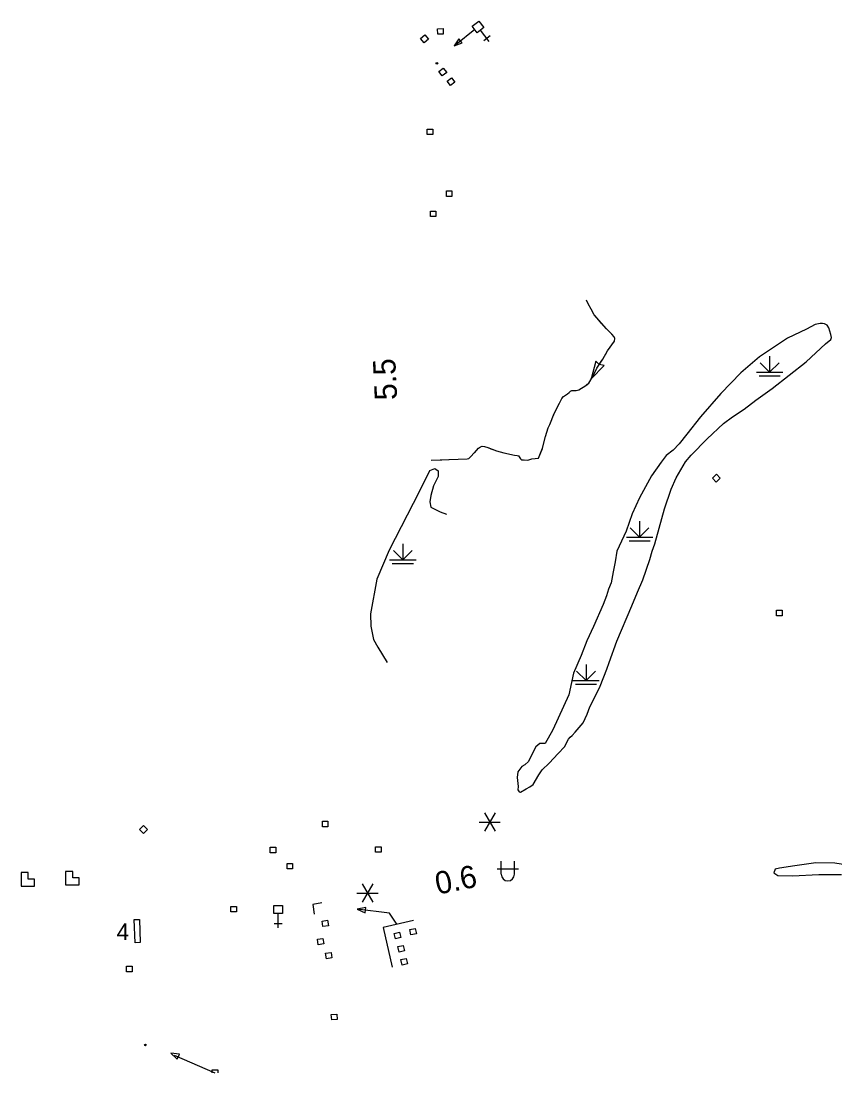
# Model space of a CAD drawing. Extents: x -160 to 6143532, y -375 to 762199.
# Drawn here: x -104.53 to -72.79, y -313.76 to -272.74 of the extents above; entities that cross this region are included whole.
import ezdxf

# ---------------------------------------------------------------- set-up
doc = ezdxf.new("R2010")
doc.units = 0
for name, color, linetype in [('Level 43', 7, 'Continuous'), ('Level 44', 7, 'Continuous'), ('Level 47', 7, 'Continuous'), ('Level 48', 7, 'Continuous'), ('Level 56', 7, 'Continuous'), ('Level 57', 7, 'Continuous'), ('Level 58', 7, 'Continuous')]:
    doc.layers.add(name, color=color, linetype=linetype)

msp = doc.modelspace()

# ---------------------------------------------------------------- linework, layer by layer
at = {"layer": 'Level 43'}
for p, q in [((-82.115, -285.996), (-82.289, -286.685)), ((-82.289, -286.685), (-81.794, -286.175)), ((-81.98, -286.128), (-82.115, -285.996)), ((-81.794, -286.175), (-81.978, -286.129))]:
    msp.add_line(p, q, dxfattribs=at)
for points in [[(-84.352, -289.786), (-84.19, -289.392), (-84.077, -288.931), (-83.976, -288.598), (-83.911, -288.463), (-83.735, -288.046), (-83.529, -287.635), (-83.443, -287.452), (-83.376, -287.38), (-83.214, -287.279), (-83.151, -287.216), (-83.099, -287.173), (-83.052, -287.146), (-82.975, -287.139), (-82.878, -287.142), (-82.779, -287.121), (-82.507, -286.953), (-82.392, -286.858), (-82.221, -286.571), (-82.075, -286.267), (-81.844, -285.923), (-81.652, -285.594), (-81.391, -285.221), (-81.367, -285.111), (-81.398, -285.052), (-81.493, -284.948), (-81.702, -284.744), (-82.176, -284.194), (-82.3, -283.972), (-82.415, -283.758), (-82.471, -283.617)], [(-82.282, -284.004), (-82.3, -283.972), (-82.415, -283.758), (-82.471, -283.617)], [(-81.873, -284.546), (-82.141, -284.236)], [(-81.596, -284.847), (-81.702, -284.744), (-81.873, -284.546)], [(-81.739, -285.743), (-81.652, -285.594), (-81.391, -285.221), (-81.367, -285.111), (-81.398, -285.052), (-81.406, -285.043)], [(-82.289, -286.685), (-82.221, -286.571), (-82.075, -286.267), (-81.88, -285.977)], [(-83.168, -287.234), (-83.151, -287.216), (-83.099, -287.173), (-83.052, -287.146), (-82.975, -287.139), (-82.878, -287.142), (-82.779, -287.121), (-82.507, -286.953), (-82.447, -286.903)], [(-83.765, -288.117), (-83.735, -288.046), (-83.529, -287.635), (-83.443, -287.452), (-83.388, -287.393)], [(-84.129, -289.143), (-84.077, -288.931), (-83.976, -288.598), (-83.911, -288.463), (-83.871, -288.368)], [(-88.529, -289.864), (-87.125, -289.805), (-87.067, -289.792), (-86.999, -289.729), (-86.684, -289.396), (-86.608, -289.342), (-86.54, -289.319), (-86.455, -289.324), (-86.329, -289.369), (-85.991, -289.499), (-85.699, -289.576), (-85.285, -289.67), (-85.179, -289.675), (-85.125, -289.693), (-85.102, -289.724), (-85.052, -289.809), (-85.007, -289.843), (-84.93, -289.847), (-84.782, -289.854), (-84.728, -289.852), (-84.608, -289.802), (-84.352, -289.786)], [(-86.85, -289.571), (-86.684, -289.396), (-86.608, -289.342), (-86.54, -289.319), (-86.455, -289.324), (-86.329, -289.369), (-86.148, -289.439)], [(-85.889, -289.526), (-85.699, -289.576), (-85.285, -289.67), (-85.179, -289.675), (-85.125, -289.693), (-85.105, -289.721)], [(-84.352, -289.786), (-84.196, -289.408)], [(-88.529, -289.864), (-88.12, -289.847)], [(-87.847, -289.836), (-87.125, -289.805), (-87.067, -289.792), (-87.04, -289.767)], [(-84.893, -289.849), (-84.782, -289.854), (-84.728, -289.852), (-84.608, -289.802), (-84.352, -289.786)]]:
    msp.add_lwpolyline(points, dxfattribs=at)
at = {"layer": 'Level 44'}
for p, q in [((-75.335, -285.805), (-75.335, -286.425)), ((-75.335, -286.425), (-75.701, -286.06)), ((-75.335, -286.425), (-74.969, -286.06)), ((-75.852, -286.425), (-74.818, -286.425)), ((-75.749, -286.566), (-74.921, -286.566)), ((-80.405, -292.242), (-80.405, -292.862)), ((-80.922, -292.862), (-79.888, -292.862)), ((-80.405, -292.862), (-80.771, -292.497)), ((-80.405, -292.862), (-80.04, -292.497)), ((-89.635, -293.128), (-89.635, -293.748)), ((-80.819, -293.003), (-79.992, -293.003)), ((-89.635, -293.748), (-90.001, -293.382)), ((-89.635, -293.748), (-89.269, -293.382)), ((-90.152, -293.748), (-89.118, -293.748)), ((-90.049, -293.889), (-89.221, -293.889)), ((-82.496, -298.452), (-82.862, -298.086)), ((-82.496, -297.831), (-82.496, -298.452)), ((-82.496, -298.452), (-82.13, -298.086)), ((-83.013, -298.452), (-81.979, -298.452)), ((-82.91, -298.593), (-82.082, -298.593))]:
    msp.add_line(p, q, dxfattribs=at)
at = {"layer": 'Level 47'}
for points in [[(-73.027, -284.698), (-73.098, -284.597), (-73.202, -284.544), (-73.275, -284.536), (-73.362, -284.536), (-73.554, -284.572), (-73.892, -284.752), (-74.638, -285.102), (-75.735, -285.827), (-76.46, -286.449), (-77.236, -287.263), (-78.037, -288.176), (-78.57, -288.841), (-78.864, -289.221), (-79.092, -289.47), (-79.376, -289.683), (-79.559, -289.937), (-79.945, -290.465), (-80.411, -291.328), (-80.7, -291.952), (-80.929, -292.627), (-81.289, -293.408), (-81.36, -293.825), (-81.441, -294.211), (-81.511, -294.65), (-81.615, -294.893), (-81.702, -295.152), (-81.827, -295.494), (-82.203, -296.349), (-82.46, -296.9), (-82.688, -297.48), (-82.987, -298.166), (-83.163, -299.009), (-83.795, -300.38), (-84.094, -300.904), (-84.292, -300.909), (-84.454, -301.041), (-84.535, -301.178), (-84.733, -301.605), (-84.88, -301.742), (-84.992, -301.802), (-85.154, -302.011), (-85.174, -302.234), (-85.139, -302.589), (-85.154, -302.711), (-85.103, -302.792), (-85.053, -302.802), (-84.824, -302.68), (-84.692, -302.604), (-84.555, -302.508), (-84.337, -302.132), (-84.21, -301.94), (-83.926, -301.671), (-83.587, -301.3), (-83.333, -301.036), (-83.181, -300.742), (-83.115, -300.661), (-83.034, -300.595), (-82.917, -300.468), (-82.612, -300.109), (-82.445, -299.765), (-82.341, -299.476), (-82.161, -299.132), (-81.95, -298.675), (-81.684, -298.009), (-81.593, -297.75), (-81.3, -296.918), (-80.703, -295.536), (-80.485, -295.003), (-80.277, -294.526), (-80.013, -293.738), (-79.912, -293.403), (-79.815, -293.119), (-79.638, -292.51), (-79.44, -291.764), (-79.181, -290.993), (-78.978, -290.551), (-78.618, -289.927), (-78.4, -289.663), (-77.774, -289.024), (-77.135, -288.425), (-76.789, -288.166), (-76.328, -287.867), (-75.876, -287.517), (-75.238, -287.068), (-73.914, -286.023), (-73.156, -285.322), (-72.943, -285.155), (-72.917, -285.074), (-72.948, -284.963), (-73.027, -284.698)], [(-88.582, -290.262), (-89.233, -291.545), (-90.171, -293.365), (-90.65, -294.495), (-90.899, -295.855), (-90.88, -296.334), (-90.784, -296.852), (-90.612, -297.158), (-90.255, -297.75)], [(-88.582, -290.262), (-88.39, -290.185), (-88.256, -290.281), (-88.256, -290.491), (-88.448, -290.855), (-88.544, -291.239), (-88.582, -291.488), (-88.544, -291.698), (-88.18, -291.871), (-87.933, -291.964)], [(-71.641, -305.759), (-72.796, -305.578), (-73.537, -305.561), (-74.347, -305.682), (-74.95, -305.768), (-74.95, -305.768), (-75.122, -305.811), (-75.166, -305.958), (-75.01, -306.052), (-74.45, -306.07), (-73.416, -306.018), (-72.537, -306.018)]]:
    msp.add_lwpolyline(points, dxfattribs=at)
at = {"layer": 'Level 48'}
for p, q in [((-86.044, -303.617), (-86.458, -304.334)), ((-86.458, -303.617), (-86.044, -304.334)), ((-86.665, -303.976), (-85.838, -303.976)), ((-90.811, -306.383), (-91.224, -307.099)), ((-91.224, -306.383), (-90.811, -307.099)), ((-91.431, -306.741), (-90.604, -306.741))]:
    msp.add_line(p, q, dxfattribs=at)
at = {"layer": 'Level 56'}
for points in [[(-88.07, -273.027), (-88.061, -273.242), (-88.276, -273.251), (-88.285, -273.036)], [(-88.642, -273.445), (-88.807, -273.584), (-88.946, -273.419), (-88.781, -273.28)], [(-87.929, -274.745), (-88.101, -274.875), (-88.231, -274.703), (-88.06, -274.573)], [(-87.609, -275.124), (-87.781, -275.254), (-87.911, -275.082), (-87.74, -274.952)], [(-88.691, -277.167), (-88.691, -276.952), (-88.475, -276.952), (-88.475, -277.167)], [(-87.942, -279.577), (-87.942, -279.361), (-87.726, -279.361), (-87.726, -279.577)], [(-88.562, -280.361), (-88.562, -280.145), (-88.346, -280.145), (-88.346, -280.361)], [(-77.262, -290.564), (-77.417, -290.713), (-77.567, -290.558), (-77.412, -290.408)], [(-75.066, -295.928), (-75.066, -295.713), (-74.85, -295.713), (-74.85, -295.928)], [(-92.775, -304.159), (-92.775, -303.944), (-92.559, -303.944), (-92.559, -304.159)], [(-99.754, -304.109), (-99.598, -304.258), (-99.748, -304.414), (-99.903, -304.265)], [(-94.807, -305.169), (-94.807, -304.954), (-94.591, -304.954), (-94.591, -305.169)], [(-90.699, -305.152), (-90.699, -304.937), (-90.483, -304.937), (-90.483, -305.152)], [(-94.153, -305.799), (-94.153, -305.584), (-93.937, -305.584), (-93.937, -305.799)], [(-96.344, -307.476), (-96.344, -307.26), (-96.128, -307.26), (-96.128, -307.476)], [(-91.112, -307.508), (-91.086, -307.299), (-91.413, -307.364)], [(-99.875, -308.67), (-100.082, -308.678), (-100.116, -307.774), (-99.91, -307.766)], [(-92.789, -307.837), (-92.576, -307.802), (-92.542, -308.015), (-92.754, -308.05)], [(-89.93, -308.522), (-89.977, -308.312), (-89.767, -308.265), (-89.719, -308.475)], [(-89.322, -308.376), (-89.369, -308.166), (-89.158, -308.118), (-89.111, -308.328)], [(-92.972, -308.543), (-92.76, -308.508), (-92.725, -308.722), (-92.938, -308.756)], [(-89.783, -309.041), (-89.831, -308.831), (-89.62, -308.783), (-89.573, -308.993)], [(-92.649, -309.09), (-92.437, -309.056), (-92.402, -309.269), (-92.615, -309.303)], [(-89.671, -309.548), (-89.718, -309.338), (-89.507, -309.29), (-89.46, -309.5)], [(-100.409, -309.813), (-100.409, -309.598), (-100.193, -309.598), (-100.193, -309.813)], [(-92.214, -311.461), (-92.198, -311.676), (-92.413, -311.691), (-92.429, -311.477)], [(-98.435, -313.213), (-98.351, -313.02), (-98.683, -312.991)]]:
    msp.add_lwpolyline(points, close=True, dxfattribs=at)
for points in [[(-92.799, -307.127), (-93.148, -307.184), (-93.092, -307.567)], [(-89.869, -307.95), (-90.162, -307.522), (-91.413, -307.364)], [(-89.218, -307.817), (-90.41, -308.085), (-90.055, -309.626)], [(-98.549, -313.067), (-96.963, -313.755)], [(-97.068, -313.757), (-97.068, -313.639), (-96.852, -313.639), (-96.852, -313.757)]]:
    msp.add_lwpolyline(points, dxfattribs=at)
msp.add_circle((-99.677, -312.666), 0.031, dxfattribs=at)
at = {"layer": 'Level 57'}
for p, q in [((-86.267, -273.536), (-86.607, -273.094)), ((-86.239, -273.318), (-86.485, -273.507)), ((-85.803, -306.009), (-85.803, -305.492)), ((-85.286, -306.009), (-85.286, -305.492)), ((-85.958, -305.802), (-85.131, -305.802)), ((-94.505, -308.1), (-94.505, -307.543)), ((-94.35, -307.944), (-94.661, -307.944))]:
    msp.add_line(p, q, dxfattribs=at)
for points in [[(-86.67, -272.736), (-86.474, -272.992), (-86.739, -273.196), (-86.936, -272.94)], [(-87.325, -273.589), (-87.459, -273.426), (-87.637, -273.709)], [(-94.337, -307.22), (-94.337, -307.543), (-94.672, -307.543), (-94.672, -307.22)]]:
    msp.add_lwpolyline(points, close=True, dxfattribs=at)
msp.add_lwpolyline([(-87.568, -273.657), (-86.835, -273.053)], dxfattribs=at)
msp.add_circle((-88.311, -274.383), 0.031, dxfattribs=at)
msp.add_arc((-85.545, -306.009), 0.259, 180, 0, dxfattribs=at)
at = {"layer": 'Level 58'}
for points in [[(-104.526, -306.472), (-104.001, -306.472), (-104.001, -306.195), (-104.249, -306.195), (-104.249, -305.946), (-104.526, -305.946)], [(-102.789, -306.422), (-102.264, -306.422), (-102.264, -306.145), (-102.512, -306.145), (-102.512, -305.897), (-102.789, -305.897)]]:
    msp.add_lwpolyline(points, close=True, dxfattribs=at)

# ---------------------------------------------------------------- texts
at = {"layer": 'Level 48'}
for s, rotation, p in [('5.5', 92.8335, (-89.857, -287.498)), ('0.6', 11.3121, (-88.284, -306.806))]:
    msp.add_text(s, height=0.8737, rotation=rotation, dxfattribs=at).set_placement(p)
at = {"layer": 'Level 56'}
msp.add_text('4', height=0.655, dxfattribs=at).set_placement((-100.799, -308.578))

doc.saveas('drawing.dxf')
